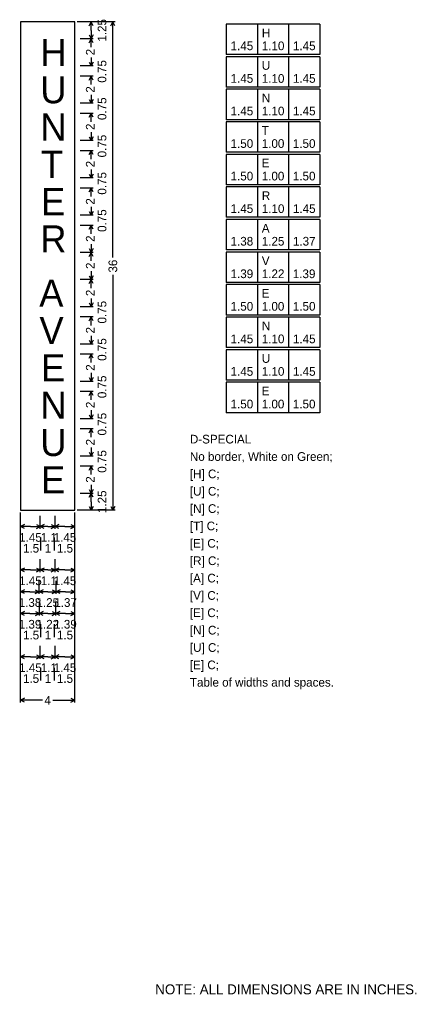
# Model space of a CAD drawing. Extents: x -16.4 to 26.5, y -12.9 to 9.1.
# Drawn here: x 20.91 to 26.48, y -11.08 to 2.61 of the extents above; entities that cross this region are included whole.
import ezdxf

# ---------------------------------------------------------------- set-up
doc = ezdxf.new("R2010")
doc.units = 0
doc.layers.add('PM_P_Text', color=7, linetype='Continuous')
doc.layers.add('SH_Text', color=7, linetype='Continuous')

msp = doc.modelspace()

# ---------------------------------------------------------------- linework, layer by layer
at = {"layer": 'SH_Text'}
for p, q in [((22.253, 2.573), (21.719, 2.573)), ((21.948, 2.573), (21.765, 2.573)), ((21.89, 2.519), (21.917, 2.573)), ((21.917, 2.454), (21.917, 2.573)), ((21.945, 2.519), (21.917, 2.573)), ((22.195, 2.519), (22.222, 2.573)), ((22.222, -0.734), (22.222, 2.573)), ((22.249, 2.519), (22.222, 2.573)), ((23.813, 2.541), (23.813, 2.115)), ((25.126, 2.541), (23.813, 2.541)), ((24.251, 2.541), (24.251, 2.115)), ((24.688, 2.541), (24.688, 2.115)), ((25.126, 2.541), (25.126, 2.115)), ((21.948, 2.335), (21.765, 2.335)), ((21.89, 2.39), (21.917, 2.335)), ((21.89, 2.281), (21.917, 2.335)), ((21.917, 2.454), (21.917, 2.335)), ((21.945, 2.39), (21.917, 2.335)), ((21.917, 2.217), (21.917, 2.335)), ((21.945, 2.281), (21.917, 2.335)), ((21.917, 2.072), (21.917, 1.954)), ((25.126, 2.115), (23.813, 2.115)), ((23.813, 2.084), (23.813, 1.657)), ((25.126, 2.084), (23.813, 2.084)), ((24.251, 2.084), (24.251, 1.657)), ((24.688, 2.084), (24.688, 1.657)), ((25.126, 2.084), (25.126, 1.657)), ((21.948, 1.954), (21.765, 1.954)), ((21.89, 2.009), (21.917, 1.954)), ((21.945, 2.009), (21.917, 1.954)), ((21.948, 1.811), (21.765, 1.811)), ((21.89, 1.757), (21.917, 1.811)), ((21.917, 1.693), (21.917, 1.811)), ((21.945, 1.757), (21.917, 1.811)), ((25.126, 1.657), (23.813, 1.657)), ((21.917, 1.549), (21.917, 1.43)), ((23.813, 1.627), (23.813, 1.2)), ((25.126, 1.627), (23.813, 1.627)), ((24.251, 1.627), (24.251, 1.2)), ((24.688, 1.627), (24.688, 1.2)), ((25.126, 1.627), (25.126, 1.2)), ((21.948, 1.43), (21.765, 1.43)), ((21.89, 1.485), (21.917, 1.43)), ((21.945, 1.485), (21.917, 1.43)), ((21.948, 1.287), (21.765, 1.287)), ((21.89, 1.233), (21.917, 1.287)), ((21.917, 1.169), (21.917, 1.287)), ((21.945, 1.233), (21.917, 1.287)), ((25.126, 1.2), (23.813, 1.2)), ((23.813, 1.17), (23.813, 0.743)), ((25.124, 1.17), (23.813, 1.17)), ((24.25, 1.17), (24.25, 0.743)), ((24.687, 1.17), (24.687, 0.743)), ((25.124, 1.17), (25.124, 0.743)), ((21.89, 0.961), (21.917, 0.906)), ((21.917, 1.025), (21.917, 0.906)), ((21.945, 0.961), (21.917, 0.906)), ((21.948, 0.906), (21.765, 0.906)), ((21.948, 0.763), (21.765, 0.763)), ((21.89, 0.709), (21.917, 0.763)), ((21.917, 0.645), (21.917, 0.763)), ((21.945, 0.709), (21.917, 0.763)), ((25.124, 0.743), (23.813, 0.743)), ((23.813, 0.713), (23.813, 0.286)), ((25.124, 0.713), (23.813, 0.713)), ((24.25, 0.713), (24.25, 0.286)), ((24.687, 0.713), (24.687, 0.286)), ((25.124, 0.713), (25.124, 0.286)), ((21.89, 0.437), (21.917, 0.382)), ((21.917, 0.501), (21.917, 0.382)), ((21.945, 0.437), (21.917, 0.382)), ((21.948, 0.382), (21.765, 0.382)), ((25.124, 0.286), (23.813, 0.286)), ((21.948, 0.24), (21.765, 0.24)), ((21.89, 0.185), (21.917, 0.24)), ((21.917, 0.121), (21.917, 0.24)), ((21.945, 0.185), (21.917, 0.24)), ((23.813, 0.255), (23.813, -0.171)), ((25.126, 0.255), (23.813, 0.255)), ((24.251, 0.255), (24.251, -0.171)), ((24.688, 0.255), (24.688, -0.171)), ((25.126, 0.255), (25.126, -0.171)), ((21.89, -0.087), (21.917, -0.141)), ((21.917, -0.023), (21.917, -0.141)), ((21.945, -0.087), (21.917, -0.141)), ((21.948, -0.141), (21.765, -0.141)), ((25.126, -0.171), (23.813, -0.171)), ((23.813, -0.202), (23.813, -0.629)), ((25.126, -0.202), (23.813, -0.202)), ((24.251, -0.202), (24.251, -0.629)), ((24.688, -0.202), (24.688, -0.629)), ((25.126, -0.202), (25.126, -0.629)), ((21.948, -0.284), (21.765, -0.284)), ((21.89, -0.339), (21.917, -0.284)), ((21.917, -0.403), (21.917, -0.284)), ((21.945, -0.339), (21.917, -0.284)), ((21.917, -0.547), (21.917, -0.665)), ((21.948, -0.665), (21.765, -0.665)), ((21.89, -0.611), (21.917, -0.665)), ((21.89, -0.72), (21.917, -0.665)), ((21.945, -0.611), (21.917, -0.665)), ((21.917, -0.784), (21.917, -0.665)), ((21.945, -0.72), (21.917, -0.665)), ((25.126, -0.629), (23.813, -0.629)), ((23.813, -0.659), (23.813, -1.086)), ((25.124, -0.659), (23.813, -0.659)), ((24.251, -0.659), (24.251, -1.086)), ((24.686, -0.659), (24.686, -1.086)), ((25.124, -0.659), (25.124, -1.086)), ((21.917, -0.928), (21.917, -1.046)), ((21.948, -1.046), (21.765, -1.046)), ((21.89, -0.992), (21.917, -1.046)), ((21.89, -1.101), (21.917, -1.046)), ((21.945, -0.992), (21.917, -1.046)), ((21.917, -1.165), (21.917, -1.046)), ((21.945, -1.101), (21.917, -1.046)), ((22.222, -0.977), (22.222, -4.285)), ((25.124, -1.086), (23.813, -1.086)), ((23.813, -1.116), (23.813, -1.543)), ((25.124, -1.116), (23.813, -1.116)), ((24.25, -1.116), (24.25, -1.543)), ((24.687, -1.116), (24.687, -1.543)), ((25.124, -1.116), (25.124, -1.543)), ((21.917, -1.309), (21.917, -1.427)), ((21.948, -1.427), (21.765, -1.427)), ((21.89, -1.373), (21.917, -1.427)), ((21.945, -1.373), (21.917, -1.427)), ((21.948, -1.57), (21.765, -1.57)), ((21.89, -1.625), (21.917, -1.57)), ((21.917, -1.688), (21.917, -1.57)), ((21.945, -1.625), (21.917, -1.57)), ((25.124, -1.543), (23.813, -1.543)), ((23.813, -1.573), (23.813, -2)), ((25.126, -1.573), (23.813, -1.573)), ((24.251, -1.573), (24.251, -2)), ((24.688, -1.573), (24.688, -2)), ((25.126, -1.573), (25.126, -2)), ((21.89, -1.897), (21.917, -1.951)), ((21.917, -1.833), (21.917, -1.951)), ((21.945, -1.897), (21.917, -1.951)), ((21.948, -1.951), (21.765, -1.951)), ((25.126, -2), (23.813, -2)), ((23.813, -2.031), (23.813, -2.457)), ((25.126, -2.031), (23.813, -2.031)), ((24.251, -2.031), (24.251, -2.457)), ((24.688, -2.031), (24.688, -2.457)), ((25.126, -2.031), (25.126, -2.457)), ((21.948, -2.094), (21.765, -2.094)), ((21.89, -2.148), (21.917, -2.094)), ((21.917, -2.212), (21.917, -2.094)), ((21.945, -2.148), (21.917, -2.094)), ((21.89, -2.421), (21.917, -2.475)), ((21.917, -2.357), (21.917, -2.475)), ((21.945, -2.421), (21.917, -2.475)), ((25.126, -2.457), (23.813, -2.457)), ((21.948, -2.475), (21.765, -2.475)), ((23.813, -2.488), (23.813, -2.915)), ((25.124, -2.488), (23.813, -2.488)), ((24.25, -2.488), (24.25, -2.915)), ((24.687, -2.488), (24.687, -2.915)), ((25.124, -2.488), (25.124, -2.915)), ((21.948, -2.618), (21.765, -2.618)), ((21.89, -2.672), (21.917, -2.618)), ((21.917, -2.736), (21.917, -2.618)), ((21.945, -2.672), (21.917, -2.618)), ((21.948, -2.999), (21.765, -2.999)), ((21.89, -2.944), (21.917, -2.999)), ((21.917, -2.881), (21.917, -2.999)), ((21.945, -2.944), (21.917, -2.999)), ((25.124, -2.915), (23.813, -2.915)), ((21.948, -3.142), (21.765, -3.142)), ((21.89, -3.196), (21.917, -3.142)), ((21.917, -3.26), (21.917, -3.142)), ((21.945, -3.196), (21.917, -3.142)), ((21.917, -3.404), (21.917, -3.523)), ((21.948, -3.523), (21.765, -3.523)), ((21.89, -3.468), (21.917, -3.523)), ((21.945, -3.468), (21.917, -3.523)), ((21.948, -3.666), (21.765, -3.666)), ((21.89, -3.72), (21.917, -3.666)), ((21.917, -3.784), (21.917, -3.666)), ((21.945, -3.72), (21.917, -3.666)), ((21.917, -3.928), (21.917, -4.047)), ((21.948, -4.047), (21.765, -4.047)), ((21.948, -4.047), (21.765, -4.047)), ((21.89, -3.992), (21.917, -4.047)), ((21.89, -4.101), (21.917, -4.047)), ((21.945, -3.992), (21.917, -4.047)), ((21.917, -4.166), (21.917, -4.047)), ((21.945, -4.101), (21.917, -4.047)), ((21.89, -4.23), (21.917, -4.285)), ((21.917, -4.166), (21.917, -4.285)), ((21.945, -4.23), (21.917, -4.285)), ((22.195, -4.23), (22.222, -4.285)), ((22.249, -4.23), (22.222, -4.285)), ((20.927, -6.982), (20.927, -4.315)), ((20.927, -4.544), (20.927, -4.361)), ((21.204, -4.544), (21.204, -4.361)), ((21.412, -4.544), (21.412, -4.361)), ((21.412, -4.544), (21.412, -4.361)), ((21.689, -6.982), (21.689, -4.315)), ((21.689, -4.544), (21.689, -4.361)), ((22.253, -4.285), (21.719, -4.285)), ((21.948, -4.285), (21.765, -4.285)), ((20.981, -4.486), (20.927, -4.513)), ((21.065, -4.513), (20.927, -4.513)), ((20.981, -4.541), (20.927, -4.513)), ((21.065, -4.513), (21.204, -4.513)), ((21.149, -4.486), (21.204, -4.513)), ((21.149, -4.541), (21.204, -4.513)), ((21.258, -4.486), (21.204, -4.513)), ((21.308, -4.513), (21.204, -4.513)), ((21.258, -4.541), (21.204, -4.513)), ((21.308, -4.513), (21.412, -4.513)), ((21.358, -4.486), (21.412, -4.513)), ((21.358, -4.541), (21.412, -4.513)), ((21.466, -4.486), (21.412, -4.513)), ((21.55, -4.513), (21.412, -4.513)), ((21.466, -4.541), (21.412, -4.513)), ((21.55, -4.513), (21.689, -4.513)), ((21.634, -4.486), (21.689, -4.513)), ((21.634, -4.541), (21.689, -4.513)), ((20.927, -4.849), (20.927, -4.666)), ((21.213, -4.849), (21.213, -4.666)), ((21.403, -4.849), (21.403, -4.666)), ((21.403, -4.849), (21.403, -4.666)), ((21.689, -4.849), (21.689, -4.666)), ((20.927, -5.153), (20.927, -4.971)), ((21.204, -5.153), (21.204, -4.971)), ((21.412, -5.153), (21.412, -4.971)), ((21.412, -5.153), (21.412, -4.971)), ((21.689, -5.153), (21.689, -4.971)), ((20.981, -5.096), (20.927, -5.123)), ((21.065, -5.123), (20.927, -5.123)), ((20.981, -5.15), (20.927, -5.123)), ((21.065, -5.123), (21.204, -5.123)), ((21.149, -5.096), (21.204, -5.123)), ((21.149, -5.15), (21.204, -5.123)), ((21.258, -5.096), (21.204, -5.123)), ((21.308, -5.123), (21.204, -5.123)), ((21.258, -5.15), (21.204, -5.123)), ((21.308, -5.123), (21.412, -5.123)), ((21.358, -5.096), (21.412, -5.123)), ((21.358, -5.15), (21.412, -5.123)), ((21.466, -5.096), (21.412, -5.123)), ((21.55, -5.123), (21.412, -5.123)), ((21.466, -5.15), (21.412, -5.123)), ((21.55, -5.123), (21.689, -5.123)), ((21.634, -5.096), (21.689, -5.123)), ((21.634, -5.15), (21.689, -5.123)), ((20.927, -5.458), (20.927, -5.275)), ((21.189, -5.458), (21.189, -5.275)), ((21.427, -5.458), (21.427, -5.275)), ((21.427, -5.458), (21.427, -5.275)), ((21.689, -5.458), (21.689, -5.275)), ((20.981, -5.401), (20.927, -5.428)), ((21.058, -5.428), (20.927, -5.428)), ((20.981, -5.455), (20.927, -5.428)), ((21.058, -5.428), (21.189, -5.428)), ((21.134, -5.401), (21.189, -5.428)), ((21.134, -5.455), (21.189, -5.428)), ((21.243, -5.401), (21.189, -5.428)), ((21.308, -5.428), (21.189, -5.428)), ((21.243, -5.455), (21.189, -5.428)), ((21.308, -5.428), (21.427, -5.428)), ((21.372, -5.401), (21.427, -5.428)), ((21.372, -5.455), (21.427, -5.428)), ((21.481, -5.401), (21.427, -5.428)), ((21.558, -5.428), (21.427, -5.428)), ((21.481, -5.455), (21.427, -5.428)), ((21.558, -5.428), (21.689, -5.428)), ((21.634, -5.401), (21.689, -5.428)), ((21.634, -5.455), (21.689, -5.428)), ((20.927, -5.763), (20.927, -5.58)), ((21.192, -5.763), (21.192, -5.58)), ((21.424, -5.763), (21.424, -5.58)), ((21.424, -5.763), (21.424, -5.58)), ((21.689, -5.763), (21.689, -5.58)), ((20.981, -5.705), (20.927, -5.733)), ((21.059, -5.733), (20.927, -5.733)), ((20.981, -5.76), (20.927, -5.733)), ((21.059, -5.733), (21.192, -5.733)), ((21.137, -5.705), (21.192, -5.733)), ((21.137, -5.76), (21.192, -5.733)), ((21.246, -5.705), (21.192, -5.733)), ((21.308, -5.733), (21.192, -5.733)), ((21.246, -5.76), (21.192, -5.733)), ((21.308, -5.733), (21.424, -5.733)), ((21.369, -5.705), (21.424, -5.733)), ((21.369, -5.76), (21.424, -5.733)), ((21.478, -5.705), (21.424, -5.733)), ((21.556, -5.733), (21.424, -5.733)), ((21.478, -5.76), (21.424, -5.733)), ((21.556, -5.733), (21.689, -5.733)), ((21.634, -5.705), (21.689, -5.733)), ((21.634, -5.76), (21.689, -5.733)), ((20.927, -6.068), (20.927, -5.885)), ((21.213, -6.068), (21.213, -5.885)), ((21.403, -6.068), (21.403, -5.885)), ((21.403, -6.068), (21.403, -5.885)), ((21.689, -6.068), (21.689, -5.885)), ((20.927, -6.373), (20.927, -6.19)), ((21.204, -6.373), (21.204, -6.19)), ((21.412, -6.373), (21.412, -6.19)), ((21.412, -6.373), (21.412, -6.19)), ((21.689, -6.373), (21.689, -6.19)), ((20.981, -6.315), (20.927, -6.342)), ((21.065, -6.342), (20.927, -6.342)), ((20.981, -6.369), (20.927, -6.342)), ((21.065, -6.342), (21.204, -6.342)), ((21.149, -6.315), (21.204, -6.342)), ((21.149, -6.369), (21.204, -6.342)), ((21.258, -6.315), (21.204, -6.342)), ((21.308, -6.342), (21.204, -6.342)), ((21.258, -6.369), (21.204, -6.342)), ((21.308, -6.342), (21.412, -6.342)), ((21.358, -6.315), (21.412, -6.342)), ((21.358, -6.369), (21.412, -6.342)), ((21.466, -6.315), (21.412, -6.342)), ((21.55, -6.342), (21.412, -6.342)), ((21.466, -6.369), (21.412, -6.342)), ((21.55, -6.342), (21.689, -6.342)), ((21.634, -6.315), (21.689, -6.342)), ((21.634, -6.369), (21.689, -6.342)), ((20.927, -6.677), (20.927, -6.495)), ((21.213, -6.677), (21.213, -6.495)), ((21.403, -6.677), (21.403, -6.495)), ((21.403, -6.677), (21.403, -6.495)), ((21.689, -6.677), (21.689, -6.495)), ((20.981, -6.925), (20.927, -6.952)), ((21.233, -6.952), (20.927, -6.952)), ((20.981, -6.979), (20.927, -6.952)), ((21.382, -6.952), (21.689, -6.952)), ((21.634, -6.925), (21.689, -6.952)), ((21.634, -6.979), (21.689, -6.952))]:
    msp.add_line(p, q, dxfattribs=at)
msp.add_lwpolyline([(20.927, -4.285), (21.689, -4.285), (21.689, 2.573), (20.927, 2.573), (20.927, -4.285), (20.927, -4.285)], dxfattribs=at)

# ---------------------------------------------------------------- texts
at = {"layer": 'PM_P_Text'}
msp.add_text('NOTE: ALL DIMENSIONS ARE IN INCHES.', height=0.14, dxfattribs=at).set_placement((22.817, -11.082))
at = {"layer": 'SH_Text'}
for s, height, p in [('1.25', 0.1219, (22.131, 2.296)), ('2', 0.122, (21.966, 2.103)), ('0.75', 0.1219, (22.131, 1.719)), ('2', 0.122, (21.966, 1.579)), ('0.75', 0.1219, (22.131, 1.195)), ('2', 0.122, (21.966, 1.055)), ('0.75', 0.1219, (22.131, 0.671)), ('2', 0.122, (21.966, 0.531)), ('0.75', 0.1219, (22.131, 0.147)), ('2', 0.122, (21.966, 0.007)), ('0.75', 0.1219, (22.131, -0.376)), ('2', 0.122, (21.966, -0.516)), ('2', 0.122, (21.966, -0.897)), ('36', 0.1219, (22.283, -0.947)), ('2', 0.122, (21.966, -1.278)), ('0.75', 0.1219, (22.131, -1.662)), ('2', 0.122, (21.966, -1.802)), ('0.75', 0.1219, (22.131, -2.186)), ('2', 0.122, (21.966, -2.326)), ('0.75', 0.1219, (22.131, -2.71)), ('2', 0.122, (21.966, -2.85)), ('0.75', 0.1219, (22.131, -3.234)), ('2', 0.122, (21.966, -3.374)), ('0.75', 0.1219, (22.131, -3.758)), ('2', 0.122, (21.966, -3.898)), ('1.25', 0.1219, (22.131, -4.324))]:
    msp.add_text(s, height=height, rotation=90.0002, dxfattribs=at).set_placement(p)
for s, height, p in [('H', 0.122, (24.312, 2.358)), ('H', 0.381, (21.204, 1.954)), ('1.45', 0.1219, (23.874, 2.176)), ('1.10', 0.1219, (24.312, 2.176)), ('1.45', 0.1219, (24.749, 2.176)), ('U', 0.122, (24.312, 1.901)), ('U', 0.381, (21.204, 1.43)), ('1.45', 0.1219, (23.874, 1.718)), ('1.10', 0.1219, (24.312, 1.718)), ('1.45', 0.1219, (24.749, 1.718)), ('N', 0.122, (24.312, 1.444)), ('1.45', 0.1219, (23.874, 1.261)), ('1.10', 0.1219, (24.312, 1.261)), ('1.45', 0.1219, (24.749, 1.261)), ('N', 0.381, (21.204, 0.906)), ('T', 0.122, (24.311, 0.987)), ('1.50', 0.1219, (23.874, 0.804)), ('1.00', 0.1219, (24.311, 0.804)), ('1.50', 0.1219, (24.748, 0.804)), ('T', 0.381, (21.213, 0.382)), ('E', 0.122, (24.311, 0.53)), ('1.50', 0.1219, (23.874, 0.347)), ('1.00', 0.1219, (24.311, 0.347)), ('1.50', 0.1219, (24.748, 0.347)), ('E', 0.381, (21.213, -0.141)), ('R', 0.122, (24.312, 0.072)), ('1.45', 0.1219, (23.874, -0.11)), ('1.10', 0.1219, (24.312, -0.11)), ('1.45', 0.1219, (24.749, -0.11)), ('A', 0.122, (24.312, -0.385)), ('R', 0.381, (21.204, -0.665)), ('1.38', 0.1219, (23.874, -0.568)), ('1.25', 0.1219, (24.312, -0.568)), ('1.37', 0.1219, (24.749, -0.568)), ('V', 0.122, (24.312, -0.842)), ('1.39', 0.1219, (23.874, -1.025)), ('1.22', 0.1219, (24.312, -1.025)), ('1.39', 0.1219, (24.747, -1.025)), ('A', 0.381, (21.189, -1.427)), ('E', 0.122, (24.311, -1.299)), ('1.50', 0.1219, (23.874, -1.482)), ('1.00', 0.1219, (24.311, -1.482)), ('1.50', 0.1219, (24.748, -1.482)), ('V', 0.381, (21.192, -1.951)), ('N', 0.122, (24.312, -1.756)), ('1.45', 0.1219, (23.874, -1.939)), ('1.10', 0.1219, (24.312, -1.939)), ('1.45', 0.1219, (24.749, -1.939)), ('E', 0.381, (21.213, -2.475)), ('U', 0.122, (24.312, -2.214)), ('1.45', 0.1219, (23.874, -2.396)), ('1.10', 0.1219, (24.312, -2.396)), ('1.45', 0.1219, (24.749, -2.396)), ('E', 0.122, (24.311, -2.671)), ('N', 0.381, (21.204, -2.999)), ('1.50', 0.1219, (23.874, -2.854)), ('1.00', 0.1219, (24.311, -2.854)), ('1.50', 0.1219, (24.748, -2.854)), ('U', 0.381, (21.204, -3.523)), ('D-SPECIAL', 0.1219, (23.303, -3.347)), ('No border, White on Green; ', 0.12192, (23.303, -3.591)), ('E', 0.381, (21.213, -4.047)), ('[H] C; ', 0.1219, (23.303, -3.835)), ('[U] C; ', 0.1219, (23.303, -4.079)), ('[N] C; ', 0.1219, (23.303, -4.322)), ('[T] C; ', 0.1219, (23.303, -4.566)), ('1.45', 0.1219, (20.907, -4.727)), ('1.1', 0.1219, (21.211, -4.727)), ('1.45', 0.1219, (21.392, -4.727)), ('1.5', 0.1219, (20.961, -4.879)), ('1', 0.122, (21.265, -4.879)), ('1.5', 0.1219, (21.437, -4.879)), ('[E] C; ', 0.1219, (23.303, -4.81)), ('[R] C; ', 0.1219, (23.303, -5.054)), ('[A] C; ', 0.1219, (23.303, -5.298)), ('1.45', 0.1219, (20.907, -5.336)), ('1.1', 0.1219, (21.211, -5.336)), ('1.45', 0.1219, (21.392, -5.336)), ('[V] C; ', 0.1219, (23.303, -5.542)), ('1.38', 0.1219, (20.9, -5.641)), ('1.25', 0.1219, (21.15, -5.641)), ('1.37', 0.1219, (21.4, -5.641)), ('[E] C; ', 0.1219, (23.303, -5.785)), ('1.39', 0.1219, (20.901, -5.946)), ('1.22', 0.1219, (21.151, -5.946)), ('1.39', 0.1219, (21.398, -5.946)), ('1.5', 0.1219, (20.961, -6.098)), ('1', 0.122, (21.265, -6.098)), ('1.5', 0.1219, (21.437, -6.098)), ('[N] C; ', 0.1219, (23.303, -6.029)), ('[U] C; ', 0.1219, (23.303, -6.273)), ('1.45', 0.1219, (20.907, -6.556)), ('1.1', 0.1219, (21.211, -6.556)), ('1.45', 0.1219, (21.392, -6.556)), ('[E] C; ', 0.1219, (23.303, -6.517)), ('1.5', 0.1219, (20.961, -6.708)), ('1', 0.122, (21.265, -6.708)), ('1.5', 0.1219, (21.437, -6.708)), ('Table of widths and spaces.', 0.12192, (23.303, -6.761)), ('4', 0.122, (21.262, -7.013))]:
    msp.add_text(s, height=height, dxfattribs=at).set_placement(p)

doc.saveas('drawing.dxf')
